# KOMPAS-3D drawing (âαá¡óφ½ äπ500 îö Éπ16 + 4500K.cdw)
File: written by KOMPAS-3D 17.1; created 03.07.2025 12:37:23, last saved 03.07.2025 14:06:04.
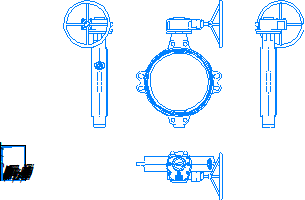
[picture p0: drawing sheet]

Sheet 1: A4, portrait

Title block, sheet 1: sheets: 1; sheet format: A4; stored path: \\adlc.lan\data\АДЛ_ПКД\3D-модели\ADL production\Дисковые поворотные затворы ГРАНВЭЛ\межфланцевый с китайским редуктором Ру16\KOMPAS 2D\Гранвэл Ду500 МФ Ру16 + 4500K.cdw

Views: Проекционный вид 2, Проекционный вид 3, Проекционный вид 4
Referenced files in \\adlc.lan\data\АДЛ_ПКД\3D-модели\ADL production\Дисковые поворотные затворы ГРАНВЭЛ\межфланцевый с китайским редуктором Ру16\KOMPAS 3D\: Гранвэл Ду500 МФ Ру16 + 4500K.m3d
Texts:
  Andrey
  АДЛ
Dimensions and other numbers on the sheet: 1:1; 1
